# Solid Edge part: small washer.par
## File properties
Author: Deepak Maini
Template: Normal.par
Last saved by: Robert a Rhodes jr
Revision: 3
Application: Solid Edge
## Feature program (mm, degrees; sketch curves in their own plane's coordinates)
sketch for "unnamed Protrusion 1" #1 plane through (0, 0, 0) normal (0, 0, 1) x-axis (1, 0, 0)
  circle centre (0, 0) radius 8
sketch for "unnamed Protrusion 1" #2 plane through (0, 0, 0) normal (0, 0, 1) x-axis (1, 0, 0)
  circle centre (0, 0) radius 17.5
extrude "unnamed Protrusion 1" add finite 5 symmetric
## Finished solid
Body 1: solid body, 4 faces, 4 edges, 0 vertices.
  Faces by surface: cylinder 2, plane 2
  Edges by curve: circle 4
Bounding box of the edges (mm): 35.000 x 35.000 x 5.000, from (-17.5, -17.5, -2.5) to (17.5, 17.5, 2.5).
Cylindrical faces by radius (mm): R8 x1, R17.5 x1
Planar faces by outward normal: +z 1, -z 1
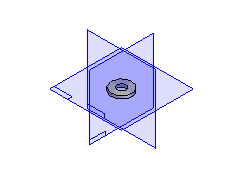
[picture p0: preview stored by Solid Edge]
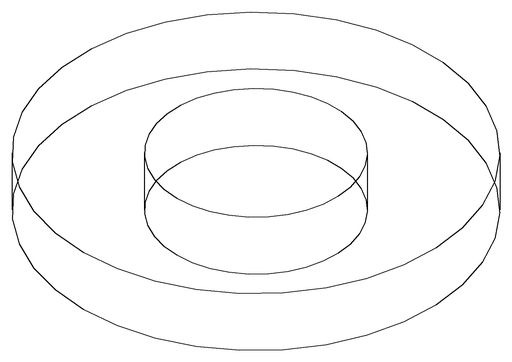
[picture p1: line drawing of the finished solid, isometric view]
